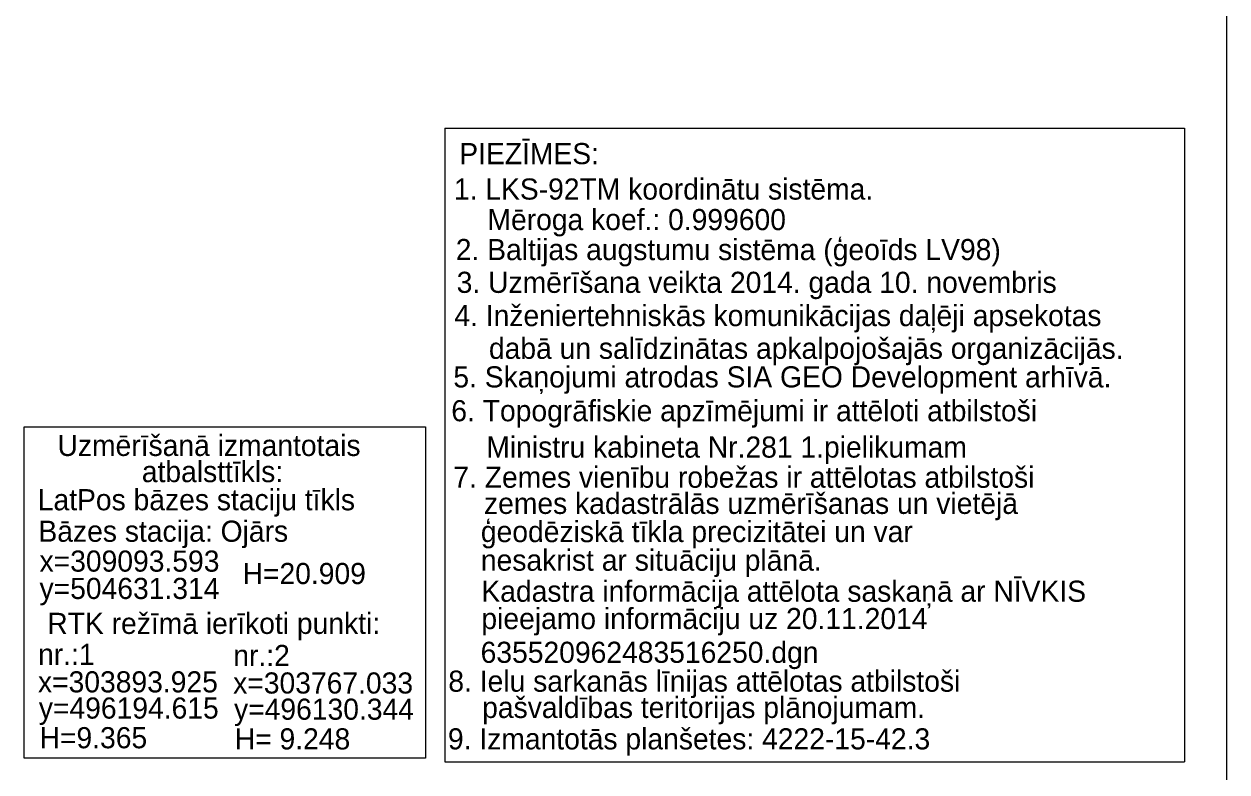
# Model space of a CAD drawing. Extents: x 496127 to 496334, y 303823 to 303967.
# Drawn here: x 496277.2 to 496334.1, y 303880.1 to 303915.5 of the extents above; entities that cross this region are included whole.
import ezdxf

# ---------------------------------------------------------------- set-up
doc = ezdxf.new("R2010")
doc.units = 0
doc.layers.add('RAMI_PLAN_####_TKST_#', color=7, linetype='Continuous')

msp = doc.modelspace()

# ---------------------------------------------------------------- linework, layer by layer
at = {"layer": 'RAMI_PLAN_####_TKST_#'}
for p, q in [((496334.105, 303822.887), (496334.105, 303966.843)), ((496297.091, 303910.578), (496297.091, 303880.584)), ((496297.091, 303910.578), (496332.091, 303910.578)), ((496332.091, 303910.578), (496332.091, 303880.584)), ((496277.179, 303896.451), (496296.175, 303896.451)), ((496277.179, 303880.767), (496277.179, 303896.451)), ((496296.175, 303896.451), (496296.175, 303880.767)), ((496296.175, 303880.767), (496277.179, 303880.767)), ((496297.091, 303880.584), (496332.091, 303880.584))]:
    msp.add_line(p, q, dxfattribs=at)

# ---------------------------------------------------------------- texts
for s, rotation, p in [('PIEZĪMES:', 0, (496297.774, 303908.881)), ('1. LKS-92TM koordinātu sistēma. ', 0, (496297.52, 303907.204)), ('Mēroga koef.: 0.999600', 0, (496299.11, 303905.758)), ('2. Baltijas augstumu sistēma (ģeoīds LV98)', 0, (496297.61, 303904.339)), ('3. Uzmērīšana veikta 2014. gada 10. novembris', 0, (496297.653, 303902.788)), ('4. Inženiertehniskās komunikācijas daļēji apsekotas', 0, (496297.543, 303901.214)), ('dabā un salīdzinātas apkalpojošajās organizācijās.', 0, (496299.179, 303899.665)), ('5. Skaņojumi atrodas SIA GEO Development arhīvā.', 0, (496297.495, 303898.312)), ('6. Topogrāfiskie apzīmējumi ir attēloti atbilstoši', 0, (496297.398, 303896.711)), ('Uzmērīšanā izmantotais ', 0, (496278.761, 303895.068)), ('    Ministru kabineta Nr.281 1.pielikumam', 0, (496297.569, 303894.99)), ('atbalsttīkls:', 0, (496282.752, 303893.829)), ('7. Zemes vienību robežas ir attēlotas atbilstoši', 0, (496297.494, 303893.564)), ('LatPos bāzes staciju tīkls', 0, (496277.828, 303892.497)), ('   zemes kadastrālās uzmērīšanas un vietējā', 0, (496297.831, 303892.325)), ('Bāzes stacija: Ojārs', 0, (496277.86, 303891.007)), ('   ģeodēziskā tīkla precizitātei un var ', 0, (496297.683, 303890.99)), ('   nesakrist ar situāciju plānā.', 0, (496297.683, 303889.636)), ('Kadastra informācija attēlota saskaņā ar NĪVKIS ', 0, (496298.822, 303888.166)), ('RTK režīmā ierīkoti punkti:', 0, (496278.277, 303886.644)), ('pieejamo informāciju uz 20.11.2014', 0, (496298.822, 303886.872)), ('635520962483516250.dgn', 0, (496298.786, 303885.275)), ('nr.:1', 0, (496277.842, 303885.179)), ('nr.:2', 0, (496287.08, 303885.125)), ('x=303893.925', 0, (496277.837, 303883.876)), ('x=303767.033', 0, (496287.075, 303883.822)), ('8. Ielu sarkanās līnijas attēlotas atbilstoši', 359.9997, (496297.257, 303883.909)), ('y=496194.615', 0, (496277.878, 303882.636)), ('y=496130.344', 0, (496287.116, 303882.582)), (' pašvaldības teritorijas plānojumam.', 359.9997, (496298.487, 303882.665)), ('H=9.365', 0, (496277.913, 303881.232)), ('H= 9.248', 0, (496287.151, 303881.177)), ('9. Izmantotās planšetes: 4222-15-42.3', 359.9997, (496297.239, 303881.178))]:
    msp.add_text(s, height=1, rotation=rotation, dxfattribs=at).set_placement(p)
for s, p in [('x=309093.593 ', (496277.912, 303889.592)), (' H=20.909', (496287.149, 303889.004)), ('y=504631.314', (496277.912, 303888.298))]:
    msp.add_text(s, height=1, dxfattribs=at).set_placement(p)

doc.saveas('drawing.dxf')
